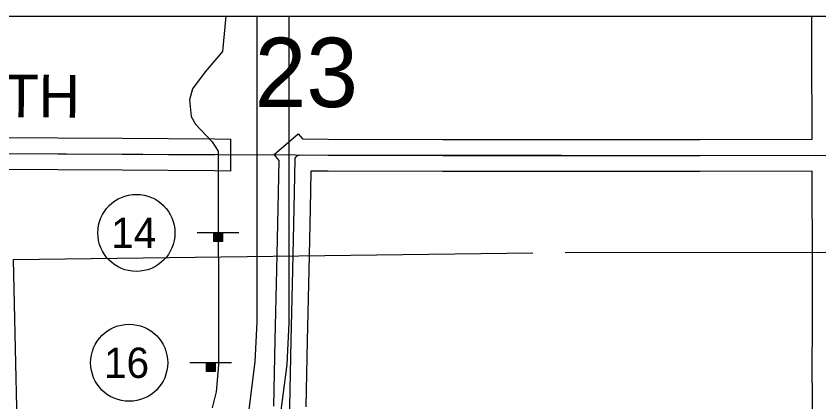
# Model space of a CAD drawing. Extents: x -2251611 to -2054719, y -2227156 to -2099355.
# Drawn here: x -2135345 to -2127401, y -2121927 to -2118110 of the extents above; entities that cross this region are included whole.
import ezdxf

# ---------------------------------------------------------------- set-up
doc = ezdxf.new("R2010")
doc.units = 0
for name, color, linetype in [('dsnTextFinalPlan', 7, 'Continuous'), ('dsnTextNote', 7, 'Continuous'), ('tdCoHydroRiver', 7, 'Continuous'), ('tdCoInt', 7, 'Continuous'), ('tdCoSecRdTxt', 7, 'Continuous'), ('tdCoSecRteBand', 7, 'Continuous'), ('tdCoSectLinePart', 7, 'Continuous'), ('tdCoSectNmbr', 7, 'Continuous'), ('tdCoSurfEarth', 7, 'Continuous'), ('tdCoSurfGravel', 7, 'Continuous'), ('tdCoTwpBndryShd', 7, 'Continuous')]:
    doc.layers.add(name, color=color, linetype=linetype)

msp = doc.modelspace()

# ---------------------------------------------------------------- linework, layer by layer
at = {"layer": 'dsnTextFinalPlan'}
for p, q in [((-2133141.4, -2120254.8), (-2133553.9, -2120254.8)), ((-2133388.1, -2120261), (-2133304.3, -2120261)), ((-2133304.3, -2120265.2), (-2133388.1, -2120265.2)), ((-2133388.1, -2120269.1), (-2133304.3, -2120269.1)), ((-2133304.3, -2120273.1), (-2133388.1, -2120273.1)), ((-2133388.1, -2120276.5), (-2133304.3, -2120276.5)), ((-2133304.3, -2120279.6), (-2133388.1, -2120279.6)), ((-2133388.1, -2120284.6), (-2133304.3, -2120284.6)), ((-2133304.3, -2120288.6), (-2133388.1, -2120288.6)), ((-2133388.1, -2120291.9), (-2133304.3, -2120291.6)), ((-2133304.3, -2120296.7), (-2133388.1, -2120296.7)), ((-2133388.1, -2120302.3), (-2133304.3, -2120302.3)), ((-2133304.3, -2120308.8), (-2133388.1, -2120308.8)), ((-2133388.1, -2120312.2), (-2133304.3, -2120311.9)), ((-2133304.3, -2120318.4), (-2133388.1, -2120318.6)), ((-2133388.1, -2120321.7), (-2133304.3, -2120321.7)), ((-2133304.3, -2120326.5), (-2133388.1, -2120326.5)), ((-2133388.1, -2120329.9), (-2133304.3, -2120329.9)), ((-2133304.3, -2120334.7), (-2133388.1, -2120334.7)), ((-2133212.8, -2121539.7), (-2133625.3, -2121539.7)), ((-2133459.5, -2121545.9), (-2133375.7, -2121545.9)), ((-2133375.7, -2121550.1), (-2133459.5, -2121550.1)), ((-2133459.5, -2121554), (-2133375.7, -2121554)), ((-2133375.7, -2121558), (-2133459.5, -2121558)), ((-2133459.5, -2121561.3), (-2133375.7, -2121561.3)), ((-2133375.7, -2121564.4), (-2133459.5, -2121564.4)), ((-2133459.5, -2121569.5), (-2133375.7, -2121569.5)), ((-2133375.7, -2121573.4), (-2133459.5, -2121573.4)), ((-2133459.5, -2121576.8), (-2133375.7, -2121576.5)), ((-2133375.7, -2121581.6), (-2133459.5, -2121581.6)), ((-2133459.5, -2121587.2), (-2133375.7, -2121587.2)), ((-2133375.7, -2121593.7), (-2133459.5, -2121593.7)), ((-2133459.5, -2121597), (-2133375.7, -2121596.8)), ((-2133375.7, -2121603.2), (-2133459.5, -2121603.5)), ((-2133459.5, -2121606.6), (-2133375.7, -2121606.6)), ((-2133375.7, -2121611.4), (-2133459.5, -2121611.4)), ((-2133459.5, -2121614.8), (-2133375.7, -2121614.8)), ((-2133375.7, -2121619.5), (-2133459.5, -2121619.5))]:
    msp.add_line(p, q, dxfattribs=at)
for points in [[(-2133388.1, -2120256.2), (-2133303.7, -2120256.2), (-2133303.7, -2120340.6), (-2133388.1, -2120340.6)], [(-2133459.5, -2121541.1), (-2133375.1, -2121541.1), (-2133375.1, -2121625.5), (-2133459.5, -2121625.5)]]:
    msp.add_lwpolyline(points, close=True, dxfattribs=at)
at = {"layer": 'dsnTextNote'}
msp.add_lwpolyline([(-2138305.1, -2118109.7), (-2124095.9, -2118109.7), (-2124095.9, -2144315.9), (-2146959.9, -2144315.9), (-2146959.9, -2118109.7), (-2138305.1, -2118109.7)], dxfattribs=at)
for centre in [(-2134154.7, -2120254.8), (-2134226.1, -2121539.7)]:
    msp.add_circle(centre, 381.4, dxfattribs=at)
at = {"layer": 'tdCoHydroRiver'}
msp.add_lwpolyline([(-2133269.9, -2118109.7), (-2133303.2, -2118461.6), (-2133475.3, -2118662.1), (-2133598.1, -2118829.1), (-2133630.1, -2118937.5), (-2133613.1, -2119104.1), (-2133571.2, -2119179), (-2133404.2, -2119353.6), (-2133345.7, -2119445.1), (-2133340.7, -2121561.4), (-2133365.1, -2121828.1), (-2133406.4, -2121986.5)], dxfattribs=at)
at = {"layer": 'tdCoInt'}
for points in [[(-2133881.8, -2124535.9), (-2133771.2, -2124239.6), (-2133284, -2122914.7), (-2133169.3, -2122575.3), (-2133046.5, -2122055.7), (-2132978.9, -2121530.2), (-2132959.2, -2121137.6), (-2132961, -2118109.7)], [(-2133543.6, -2124536.1), (-2133411.1, -2124158.6), (-2132986.2, -2123022.8), (-2132865.5, -2122665.2), (-2132734.6, -2122112.3), (-2132663, -2121556), (-2132642.4, -2121146.1), (-2132644.2, -2118109.7)]]:
    msp.add_lwpolyline(points, dxfattribs=at)
at = {"layer": 'tdCoSecRteBand'}
for points in [[(-2132793.6, -2121969.3), (-2132781.8, -2121315.7), (-2132781.8, -2121315.3), (-2132781.8, -2121315), (-2132766.2, -2120617.1), (-2132753.2, -2120013), (-2132743.1, -2119537), (-2132792.2, -2119480.2), (-2132672.5, -2119376.7), (-2132554.2, -2119274.4), (-2132509.8, -2119325.7), (-2132256.8, -2119328.1), (-2131124.6, -2119329.4), (-2131124.5, -2119329.4), (-2131124.5, -2119329.4), (-2129710.7, -2119332), (-2128577, -2119329.4), (-2128576.9, -2119329.4), (-2128576.8, -2119329.4), (-2127467.7, -2119328.1), (-2127467.7, -2119263.9), (-2127470.3, -2118501.2), (-2127470.3, -2118500.9), (-2127470.3, -2118500.6), (-2127470.3, -2118109.7)], [(-2135746.7, -2119312), (-2134931.8, -2119314.6), (-2134931.7, -2119314.6), (-2134931.6, -2119314.6), (-2134294.9, -2119317.2), (-2134294.6, -2119317.2), (-2134294.2, -2119317.2), (-2133380.2, -2119325), (-2133221.8, -2119326.4), (-2133224.5, -2119643.2), (-2133382.9, -2119641.8), (-2134296.6, -2119634), (-2134932.9, -2119631.4), (-2135747.9, -2119628.8)], [(-2127465.1, -2122324.1), (-2127465.1, -2121745.1), (-2127466.5, -2121742.3), (-2127466.4, -2121704.7), (-2127465.1, -2121068), (-2127463.8, -2120452.8), (-2127467.7, -2119790.6), (-2127467.7, -2119790.2), (-2127467.7, -2119789.7), (-2127467.7, -2119647.1), (-2127467.7, -2119644.9), (-2128576.3, -2119646.2), (-2129710.3, -2119648.8), (-2129710.7, -2119648.8), (-2129711, -2119648.8), (-2131125, -2119646.2), (-2132257.8, -2119644.9), (-2132258.4, -2119644.9), (-2132259.1, -2119644.9), (-2132428.5, -2119643.3), (-2132436.5, -2120019.8), (-2132436.5, -2120019.8), (-2132436.5, -2120019.8), (-2132449.5, -2120624), (-2132449.5, -2120624.1), (-2132449.5, -2120624.1), (-2132465.1, -2121321.7), (-2132476.8, -2121974.4)]]:
    msp.add_lwpolyline(points, dxfattribs=at)
at = {"layer": 'tdCoSectLinePart'}
for points in [[(-2135374.5, -2120517.6), (-2130230.9, -2120452)], [(-2135374.5, -2120517.6), (-2135316.4, -2123011.2)], [(-2129911.8, -2120449.8), (-2124782.8, -2120445.7)]]:
    msp.add_lwpolyline(points, dxfattribs=at)
at = {"layer": 'tdCoSurfEarth'}
msp.add_lwpolyline([(-2132636.5, -2124633.3), (-2132636.5, -2124417.5), (-2132637.8, -2123809.4), (-2132641.7, -2123237.8), (-2132641.7, -2122586.7), (-2132635.2, -2121972.1), (-2132623.5, -2121318.5), (-2132607.8, -2120620.6), (-2132594.8, -2120016.4), (-2132584.4, -2119525.5), (-2132582.1, -2119515.9), (-2132577.8, -2119506.9), (-2132571.8, -2119499), (-2132570.4, -2119497.8)], dxfattribs=at)
at = {"layer": 'tdCoSurfGravel'}
for points in [[(-2143087.4, -2119427.1), (-2142596.9, -2119431), (-2141358.1, -2119441.8), (-2140703.1, -2119443.1), (-2139648.4, -2119449.6), (-2138756.5, -2119453.5), (-2138141.9, -2119457.4), (-2137863.7, -2119459.5), (-2137467.4, -2119462.6), (-2136790.4, -2119465.2), (-2135747.4, -2119470.4), (-2134932.3, -2119473), (-2134295.6, -2119475.6), (-2133381.5, -2119483.4)], [(-2132568.8, -2119496.4), (-2132564.3, -2119492.5), (-2132555.6, -2119487.7), (-2132546.1, -2119484.8), (-2132536.2, -2119483.9), (-2132257.6, -2119486.5), (-2131124.8, -2119487.8), (-2129710.7, -2119490.4), (-2128576.6, -2119487.8), (-2127436, -2119486.5), (-2127309.3, -2119488.7)]]:
    msp.add_lwpolyline(points, dxfattribs=at)
at = {"layer": 'tdCoTwpBndryShd'}
msp.add_lwpolyline([(-2146959.9, -2119431.7), (-2143089.2, -2119427), (-2137865.5, -2119459.5), (-2132584.4, -2119484.2), (-2127311.1, -2119488.7), (-2124095.9, -2119500.8)], dxfattribs=at)

# ---------------------------------------------------------------- texts
at = {"layer": 'dsnTextNote'}
for s, p in [('14', (-2134403.8, -2120404.8)), ('16', (-2134475.2, -2121689.7))]:
    msp.add_text(s, height=300, dxfattribs=at).set_placement(p)
at = {"layer": 'tdCoSecRdTxt'}
msp.add_text('160TH', height=422.4, rotation=359.63364, dxfattribs=at).set_placement((-2136410, -2119104.2))
at = {"layer": 'tdCoSectNmbr'}
msp.add_text('23', height=686.4, rotation=0.02032, dxfattribs=at).set_placement((-2132983.2, -2119010.6))

doc.saveas('drawing.dxf')
